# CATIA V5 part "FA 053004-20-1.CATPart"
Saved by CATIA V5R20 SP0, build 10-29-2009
Part number: FA 053004-20-1
Revision: ANY
Definition: UNKNOWN
Nomenclature: FA 053004-20-1
Source: Unknown
Bounding box of the stored display mesh (mm): x -2.5 to 2.5, y -6.775 to 5.225, z -2.5 to 2.5
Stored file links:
  C:\Users\Utente\Desktop\IO LAVORO\3D X SITO CF\CUMSA\3D files FA\FA 053004-20\FA 053004-20-1.CATPart

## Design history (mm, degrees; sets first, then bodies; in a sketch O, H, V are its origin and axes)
Body1 "Cortar-Extruir3" (main body)
  Solid1: solid without history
